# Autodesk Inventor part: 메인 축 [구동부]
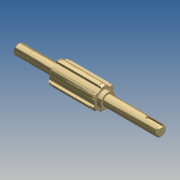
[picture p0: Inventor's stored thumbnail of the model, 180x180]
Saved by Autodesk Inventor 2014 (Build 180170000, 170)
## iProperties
Created: 2015-11
Part Number: 메인 축 [구동부]
Document SubType Name: 모델링
Designer: mdu
Mass: 168.566 g
Surface Area: 72.5104 cm^2
Volume: 21.4461 cm^3
Density: 7.86 g/cm^3
Material: 강철, 연강
Appearance: 강철
변환 표준: STEP AP214IS
파일 이름: C:\Users\SeoGD\Desktop\?쒗뿕\硫붿씤 異?.stp
전처리기: Build: 253, Release: 2010 SP1 - Date: Wed 07/29/2009
전송 단위: 밀리미터
불확실성: 0.01
Author: mdu
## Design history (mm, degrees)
sketch "스케치1"
  geometry: L1 (-69.5, 0)-(69.5, 0); L2 (69.5, 0)-(69.5, 5); L3 (69.5, 5)-(55.5, 5); L4 (55.5, 5)-(55.5, 4.8); L5 (55.5, 4.8)-(54.35, 4.8); L6 (54.35, 4.8)-(54.35, 5); L7 (54.35, 5)-(30.5, 5); L8 (30.5, 5)-(30.5, 9); L9 (30.5, 9)-(-13.5, 9); L10 (-13.5, 9)-(-13.5, 7); L11 (-13.5, 7)-(-17.5, 7); L12 (-17.5, 7)-(-17.5, 5); L13 (-17.5, 5)-(-69.5, 5); L14 (-69.5, 5)-(-69.5, 0); 2 further points
  constraints: 28 end point, 9 parallel, 4 collinear, 2 perpendicular, 1 coincident, 1 horizontal, 1 midpoint
  dimensions: "d2" = 1.15 distance between parallel lines of L6 L4; "d3" = 10 diameter of L3 L1; "d4" = 9.6 diameter of L5 L1; "d6" = 44 distance between parallel lines of L10 L8; "d7" = 4 distance between parallel lines of L12 L10; "d8" = 14 diameter of L11 L1; "d9" = 18 diameter of L9 L1; "d33" = 52 distance from line of L12.end L14; "d37" = 39 distance between parallel lines of L8 L2; "d38" = 14 distance between parallel lines of L2 L4
revolve "회전1" sketch "스케치1" stored, may be unused: angle "d10" = 90 deg
sketch "스케치2"
  geometry: L1 (2.5, 10.712)-(2.5, 8.646); L2 (-2.5, 10.712)-(-2.5, 8.646); A1 r 9 centre (0, 0) between (2.5, 8.646) and (-2.5, 8.646) reference; A2 r 11 centre (0, 0) between (2.5, 10.712) and (-2.5, 10.712); 1 further point
  constraints: 4 end point, 4 point on circle, 2 parallel, 1 centre point, 1 coincident, 1 vertical
  dimensions: "d11" = 22 diameter of A2; "d12" = 5 distance between parallel lines of L1 L2
extrude "돌출1" join sketch "스케치2" stored distance "d13" = 10; taper "d14" = 0 deg
chamfer "모따기1" distance "d15" = 1; stored, may be unused: second distance "d16" = 2, angle "d17" = 45 deg
node "작업 평면1"
node "작업 평면2"
sketch "스케치3"
  geometry: L1 (2.5, 10.712)-(2.5, 10.198); L2 (-2.5, 10.712)-(-2.5, 10.198); A1 r 11 centre (0, 0) between (2.5, 10.712) and (-2.5, 10.712) reference; A2 r 10.5 centre (0, 0) between (2.5, 10.198) and (-2.5, 10.198); 1 further point
  constraints: 4 end point, 2 point on circle, 1 centre point, 1 coincident, 1 parallel, 1 vertical
  dimensions: "d19" = 21 diameter of A2
extrude "돌출2" cut sketch "스케치3" distance "d20" = 1.35; taper "d21" = 0 deg
node "작업 평면3"
sketch "스케치4"
  geometry: L1 (-26, -5)-(-26, 5) reference; L2 (-26, 1.5)-(-12.5, 1.5); L3 (-12.5, -1.5)-(-26, -1.5); A1 r 1.5 centre (-12.5, 0) between (-12.5, -1.5) and (-12.5, 1.5); 2 further points
  constraints: 4 end point, 2 perpendicular, 2 point on circle, 2 point on line, 2 tangent, 1 centre point, 1 horizontal alignment, 1 midpoint
  dimensions: "d25" = 3 distance between parallel lines of L3 L2; "d26" = 15 dimension on A1 L1
extrude "돌출3" cut sketch "스케치4" distance "d27" = 1.8; taper "d28" = 0 deg
chamfer "모따기2" distance "d29" = 1; stored, may be unused: second distance "d30" = 2, angle "d31" = 45 deg
node "솔리드1"
node "솔리드 본체"
node "곡면 본체"
mirror "대칭1"
pattern_circular "원형 패턴1" dims "d23" = 360 deg
node "솔리드2"
other parameters: "d18" = -1.65
